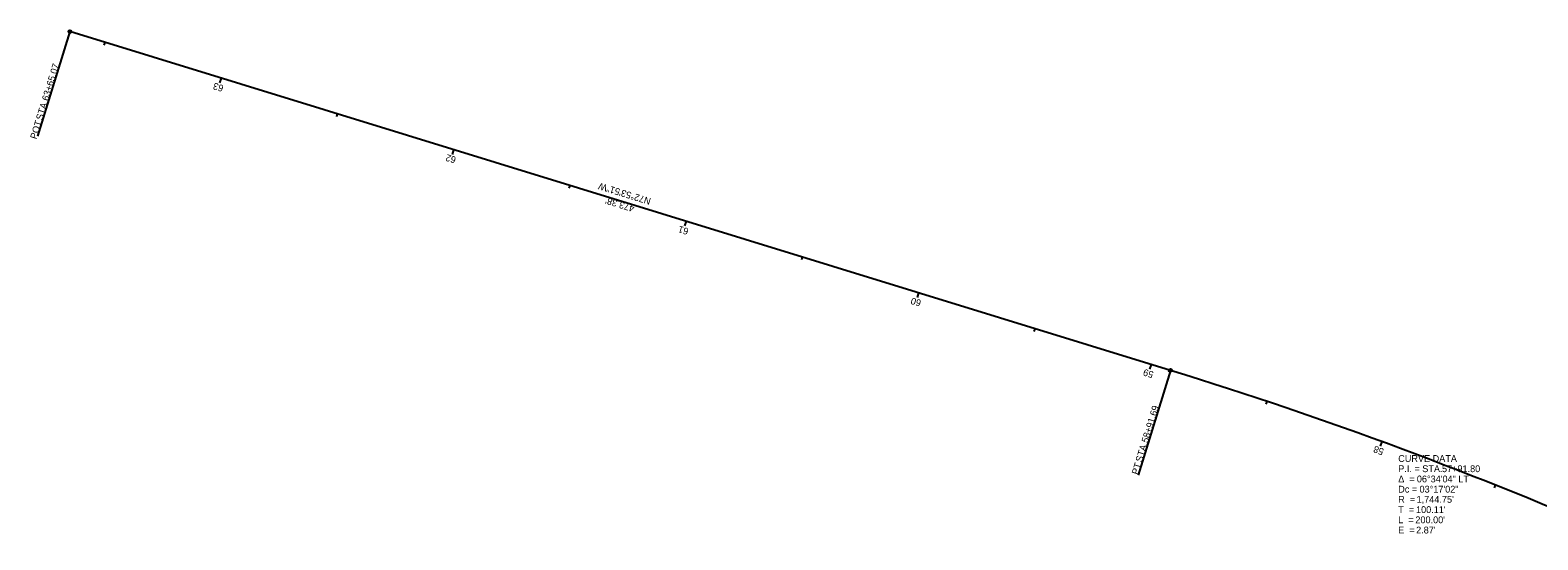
# Model space of a CAD drawing. Extents: x 1698884 to 1700452, y 716861 to 717517.
# Drawn here: x 1698884 to 1699504, y 717308 to 717517 of the extents above; entities that cross this region are included whole.
import ezdxf

# ---------------------------------------------------------------- set-up
doc = ezdxf.new("R2010")
doc.units = 0
for name, color, linetype in [('PF_X_Ground_Line', 7, 'Continuous'), ('RW_X_CL_100_Bearings', 7, 'Continuous'), ('RW_X_CL_100_Cardinal_Points', 7, 'Continuous'), ('RW_X_CL_100_Curve_Data', 7, 'Continuous'), ('RW_X_CL_100_Distances', 7, 'Continuous'), ('RW_X_CL_100_Stations', 7, 'Continuous')]:
    doc.layers.add(name, color=color, linetype=linetype)

msp = doc.modelspace()

# ---------------------------------------------------------------- linework, layer by layer
at = {"layer": 'RW_X_CL_100_Bearings'}
msp.add_line((1699352.61, 717377.52), (1698900.16, 717516.74), dxfattribs=at)
msp.add_arc((1698839.5, 715709.93), 1744.75, 66.32957, 72.89737, dxfattribs=at)
at = {"layer": 'RW_X_CL_100_Curve_Data'}
for p, q in [((1698900.16, 717516.74), (1698886.93, 717473.73)), ((1699352.61, 717377.52), (1699339.37, 717334.51))]:
    msp.add_line(p, q, dxfattribs=at)
for centre in [(1698900.16, 717516.74), (1699352.61, 717377.52)]:
    msp.add_circle(centre, 0.6, dxfattribs=at)
at = {"layer": 'RW_X_CL_100_Distances'}
for p, q in [((1698914.56, 717512.31), (1698914.21, 717511.16)), ((1698962.35, 717497.6), (1698961.76, 717495.69)), ((1699010.14, 717482.9), (1699009.79, 717481.75)), ((1699057.93, 717468.19), (1699057.34, 717466.28)), ((1699105.72, 717453.49), (1699105.37, 717452.34)), ((1699153.51, 717438.79), (1699152.92, 717436.87)), ((1699201.3, 717424.08), (1699200.94, 717422.93)), ((1699249.09, 717409.38), (1699248.5, 717407.47)), ((1699296.87, 717394.67), (1699296.52, 717393.53)), ((1699344.66, 717379.97), (1699344.08, 717378.06)), ((1699392.3, 717364.79), (1699391.92, 717363.65)), ((1699439.49, 717348.27), (1699438.81, 717346.39)), ((1699486.19, 717330.41), (1699485.75, 717329.29))]:
    msp.add_line(p, q, dxfattribs=at)

# ---------------------------------------------------------------- texts
at = {"layer": 'PF_X_Ground_Line'}
msp.add_text("473.38'", height=2.8, rotation=162.89737, dxfattribs=at).set_placement((1699132.53, 717445.2))
at = {"layer": 'RW_X_CL_100_Cardinal_Points'}
msp.add_text('N72°53\'51"W', height=2.8, rotation=162.89737, dxfattribs=at).set_placement((1699139.29, 717448.18))
at = {"layer": 'RW_X_CL_100_Curve_Data'}
for s, p in [('63+65.07', (1698891.3, 717488.07)), (' STA. ', (1698888.56, 717479.16)), ('POT', (1698886.46, 717472.34)), ('58+91.69', (1699343.34, 717347.54)), (' STA. ', (1699340.6, 717338.63)), ('PT', (1699339.32, 717334.47))]:
    msp.add_text(s, height=2.8, rotation=72.89737, dxfattribs=at).set_placement(p)
at = {"layer": 'RW_X_CL_100_Distances'}
for s, rotation, p in [('63', 162.89737, (1698963.61, 717494.6)), ('62', 162.89737, (1699059.2, 717465.19)), ('61', 162.89737, (1699154.79, 717435.78)), ('60', 162.89737, (1699250.41, 717406.36)), ('59', 162.89737, (1699345.94, 717376.96)), ('58', 159.88642, (1699440.64, 717345.19))]:
    msp.add_text(s, height=2.8, rotation=rotation, dxfattribs=at).set_placement(p)
at = {"layer": 'RW_X_CL_100_Stations'}
for s, p in [('CURVE DATA', (1699446.29, 717339.91)), ('Δ  = ', (1699446.29, 717331.51)), ('P.I. = STA. ', (1699446.29, 717335.71)), ('06°34\'04" LT', (1699453.94, 717331.51)), ('57+91.80', (1699464.28, 717335.71)), ('Dc = ', (1699446.29, 717327.31)), ('03°17\'02"', (1699455.04, 717327.31)), ('T  = ', (1699446.29, 717318.91)), ('R  = ', (1699446.29, 717323.11)), ("100.11'", (1699453.61, 717318.91)), ("1,744.75'", (1699453.83, 717323.11)), ('L  = ', (1699446.29, 717314.71)), ("200.00'", (1699453.33, 717314.71)), ('E  = ', (1699446.29, 717310.51)), ("2.87'", (1699453.64, 717310.51))]:
    msp.add_text(s, height=2.8, dxfattribs=at).set_placement(p)

doc.saveas('drawing.dxf')
